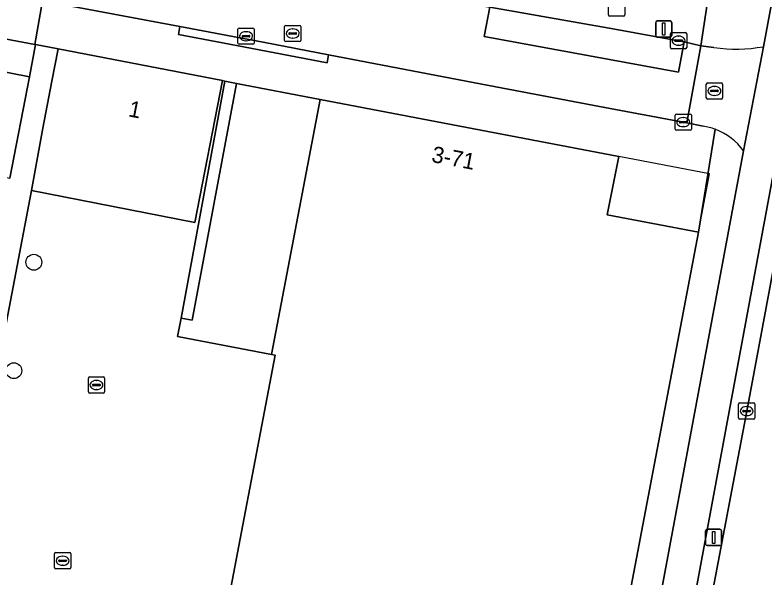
# Model space of a CAD drawing. Extents: x 161402 to 161933, y 381647 to 382315.
# Drawn here: x 161841.65 to 161887.93, y 381908.84 to 381943.55 of the extents above; entities that cross this region are included whole.
import ezdxf

# ---------------------------------------------------------------- set-up
doc = ezdxf.new("R2010")
doc.units = 0
for name, color, linetype in [('IMGEO_Boom', 7, 'Continuous'), ('IMGEO_Brandkraan', 7, 'Continuous'), ('IMGEO_Erf', 7, 'Continuous'), ('IMGEO_Fietspad_gesloten', 7, 'Continuous'), ('IMGEO_Kolk', 7, 'Continuous'), ('IMGEO_Lichtmast', 7, 'Continuous'), ('IMGEO_Pand', 7, 'Continuous'), ('IMGEO_Pand_nummerreeks', 7, 'Continuous'), ('IMGEO_Pand_overbouw', 7, 'Continuous'), ('IMGEO_Parkeervlak_open', 7, 'Continuous'), ('IMGEO_Rijbaan_lokaal_gesloten', 7, 'Continuous'), ('IMGEO_Rijbaan_lokaal_open', 7, 'Continuous'), ('IMGEO_Rioolput', 7, 'Continuous'), ('IMGEO_Verkeerseiland_open', 7, 'Continuous'), ('IMGEO_Voetpad_open', 7, 'Continuous')]:
    doc.layers.add(name, color=color, linetype=linetype)

msp = doc.modelspace()

# ---------------------------------------------------------------- linework, layer by layer
at = {"layer": 'IMGEO_Boom'}
for centre in [(161842.814, 381928.279), (161841.582, 381921.58)]:
    msp.add_circle(centre, 0.489, dxfattribs=at)
at = {"layer": 'IMGEO_Brandkraan'}
for p, q in [((161878.324, 381943.55), (161878.324, 381944.402)), ((161879.325, 381944.402), (161879.325, 381943.55)), ((161879.251, 381943.476), (161878.399, 381943.476))]:
    msp.add_line(p, q, dxfattribs=at)
for points in [[(161878.324, 381943.55), (161878.324, 381944.402)], [(161879.325, 381944.402), (161879.325, 381943.55)], [(161879.251, 381943.476), (161878.399, 381943.476)]]:
    msp.add_lwpolyline(points, dxfattribs=at)
for centre, start, end in [((161878.401, 381943.552), 181.552, 268.448), ((161878.401, 381943.552), 181.552, 268.448), ((161879.249, 381943.552), 271.552, 358.448), ((161879.249, 381943.552), 271.552, 358.448)]:
    msp.add_arc(centre, 0.0765, start, end, dxfattribs=at)
at = {"layer": 'IMGEO_Erf'}
msp.add_lwpolyline([(161838.964, 381940.425), (161842.548, 381939.733), (161842.921, 381941.724), (161842.874, 381941.733), (161832.159, 381943.741)], dxfattribs=at)
at = {"layer": 'IMGEO_Fietspad_gesloten'}
for points in [[(161910.061, 382061.001), (161905.702, 382037.375), (161898.752, 382000), (161887.89, 381941.593), (161886.669, 381935.154), (161880.56, 381902.497), (161879.486, 381896.758), (161857.65, 381780.798), (161851.928, 381750), (161842.232, 381697.819)], [(161881.54, 381896.271), (161882.623, 381902.093), (161888.398, 381933.147), (161890.059, 381942.083), (161900.83, 382000), (161908.061, 382038.88), (161912.039, 382060.567)]]:
    msp.add_lwpolyline(points, dxfattribs=at)
at = {"layer": 'IMGEO_Kolk'}
for p, q in [((161855.426, 381941.812), (161855.426, 381942.664)), ((161855.501, 381942.738), (161856.353, 381942.738)), ((161855.914, 381942.518), (161855.939, 381942.518)), ((161856.427, 381942.664), (161856.427, 381941.812)), ((161882.224, 381942.463), (161883.076, 381942.463)), ((161855.685, 381942.232), (161855.685, 381942.244)), ((161856.123, 381942.195), (161855.725, 381942.195)), ((161855.728, 381942.281), (161856.126, 381942.281)), ((161855.937, 381941.958), (161855.912, 381941.958)), ((161856.169, 381942.244), (161856.169, 381942.232)), ((161882.149, 381941.537), (161882.149, 381942.389)), ((161882.408, 381941.957), (161882.408, 381941.969)), ((161882.451, 381942.006), (161882.849, 381942.006)), ((161882.637, 381942.243), (161882.662, 381942.243)), ((161882.892, 381941.969), (161882.892, 381941.957)), ((161883.15, 381942.389), (161883.15, 381941.537)), ((161856.353, 381941.738), (161855.501, 381941.738)), ((161882.846, 381941.92), (161882.448, 381941.92)), ((161882.66, 381941.683), (161882.635, 381941.683)), ((161883.076, 381941.463), (161882.224, 381941.463)), ((161882.439, 381936.507), (161882.439, 381937.359)), ((161882.514, 381937.433), (161883.366, 381937.433)), ((161883.44, 381937.359), (161883.44, 381936.507)), ((161882.698, 381936.927), (161882.698, 381936.939)), ((161883.136, 381936.89), (161882.738, 381936.89)), ((161882.741, 381936.976), (161883.139, 381936.976)), ((161882.927, 381937.213), (161882.952, 381937.213)), ((161883.182, 381936.939), (161883.182, 381936.927)), ((161883.366, 381936.433), (161882.514, 381936.433)), ((161882.95, 381936.653), (161882.925, 381936.653)), ((161846.259, 381921.198), (161847.111, 381921.198)), ((161846.184, 381920.272), (161846.184, 381921.124)), ((161846.443, 381920.692), (161846.443, 381920.704)), ((161846.486, 381920.741), (161846.884, 381920.741)), ((161846.672, 381920.978), (161846.697, 381920.978)), ((161846.927, 381920.704), (161846.927, 381920.692)), ((161847.185, 381921.124), (161847.185, 381920.272)), ((161846.881, 381920.655), (161846.483, 381920.655)), ((161846.695, 381920.418), (161846.67, 381920.418)), ((161847.111, 381920.198), (161846.259, 381920.198)), ((161886.355, 381918.662), (161886.355, 381919.514)), ((161886.43, 381919.588), (161887.282, 381919.588)), ((161886.843, 381919.368), (161886.868, 381919.368)), ((161887.356, 381919.514), (161887.356, 381918.662)), ((161886.614, 381919.082), (161886.614, 381919.094)), ((161887.052, 381919.045), (161886.654, 381919.045)), ((161886.657, 381919.131), (161887.055, 381919.131)), ((161887.098, 381919.094), (161887.098, 381919.082)), ((161887.282, 381918.588), (161886.43, 381918.588)), ((161886.866, 381918.808), (161886.841, 381918.808)), ((161844.094, 381909.419), (161844.094, 381910.271)), ((161844.169, 381910.345), (161845.021, 381910.345)), ((161844.582, 381910.125), (161844.607, 381910.125)), ((161845.095, 381910.271), (161845.095, 381909.419)), ((161844.353, 381909.839), (161844.353, 381909.851)), ((161844.791, 381909.802), (161844.393, 381909.802)), ((161844.396, 381909.888), (161844.794, 381909.888)), ((161844.605, 381909.565), (161844.58, 381909.565)), ((161844.837, 381909.851), (161844.837, 381909.839)), ((161845.021, 381909.345), (161844.169, 381909.345))]:
    msp.add_line(p, q, dxfattribs=at)
for points in [[(161855.426, 381941.812), (161855.426, 381942.664)], [(161855.501, 381942.738), (161856.353, 381942.738)], [(161856.427, 381942.664), (161856.427, 381941.812)], [(161882.224, 381942.463), (161883.076, 381942.463)], [(161882.149, 381941.537), (161882.149, 381942.389)], [(161883.15, 381942.389), (161883.15, 381941.537)], [(161856.353, 381941.738), (161855.501, 381941.738)], [(161883.076, 381941.463), (161882.224, 381941.463)], [(161882.439, 381936.507), (161882.439, 381937.359)], [(161882.514, 381937.433), (161883.366, 381937.433)], [(161883.44, 381937.359), (161883.44, 381936.507)], [(161883.366, 381936.433), (161882.514, 381936.433)], [(161846.259, 381921.198), (161847.111, 381921.198)], [(161846.184, 381920.272), (161846.184, 381921.124)], [(161847.185, 381921.124), (161847.185, 381920.272)], [(161847.111, 381920.198), (161846.259, 381920.198)], [(161886.355, 381918.662), (161886.355, 381919.514)], [(161886.43, 381919.588), (161887.282, 381919.588)], [(161887.356, 381919.514), (161887.356, 381918.662)], [(161887.282, 381918.588), (161886.43, 381918.588)], [(161844.094, 381909.419), (161844.094, 381910.271)], [(161844.169, 381910.345), (161845.021, 381910.345)], [(161845.095, 381910.271), (161845.095, 381909.419)], [(161845.021, 381909.345), (161844.169, 381909.345)]]:
    msp.add_lwpolyline(points, dxfattribs=at)
for centre, radius, start, end in [((161855.503, 381942.662), 0.0765, 91.552, 178.448), ((161855.503, 381942.662), 0.0765, 91.552, 178.448), ((161856.351, 381942.662), 0.0765, 1.552, 88.448), ((161856.351, 381942.662), 0.0765, 1.552, 88.448), ((161882.226, 381942.387), 0.0765, 91.552, 178.448), ((161882.226, 381942.387), 0.0765, 91.552, 178.448), ((161883.074, 381942.387), 0.0765, 1.552, 88.448), ((161883.074, 381942.387), 0.0765, 1.552, 88.448), ((161855.725, 381942.241), 0.0403, 85.8775, 175.7526), ((161855.722, 381942.231), 0.0366, 178.938, 274.7102), ((161856.126, 381942.238), 0.043, 264.8664, 352.4533), ((161856.13, 381942.243), 0.0386, 1.7309, 96.639), ((161882.448, 381941.966), 0.0403, 85.8775, 175.7526), ((161882.445, 381941.956), 0.0366, 178.938, 274.7102), ((161882.849, 381941.963), 0.043, 264.8664, 352.4533), ((161882.853, 381941.968), 0.0386, 1.7309, 96.639), ((161855.503, 381941.814), 0.0765, 181.552, 268.448), ((161855.503, 381941.814), 0.0765, 181.552, 268.448), ((161856.351, 381941.814), 0.0765, 271.552, 358.448), ((161856.351, 381941.814), 0.0765, 271.552, 358.448), ((161882.226, 381941.539), 0.0765, 181.552, 268.448), ((161882.226, 381941.539), 0.0765, 181.552, 268.448), ((161883.074, 381941.539), 0.0765, 271.552, 358.448), ((161883.074, 381941.539), 0.0765, 271.552, 358.448), ((161882.516, 381937.357), 0.0765, 91.552, 178.448), ((161882.516, 381937.357), 0.0765, 91.552, 178.448), ((161883.364, 381937.357), 0.0765, 1.552, 88.448), ((161883.364, 381937.357), 0.0765, 1.552, 88.448), ((161882.738, 381936.936), 0.0403, 85.8775, 175.7526), ((161882.735, 381936.926), 0.0366, 178.938, 274.7102), ((161883.139, 381936.933), 0.043, 264.8664, 352.4533), ((161883.143, 381936.938), 0.0386, 1.7309, 96.639), ((161882.516, 381936.509), 0.0765, 181.552, 268.448), ((161882.516, 381936.509), 0.0765, 181.552, 268.448), ((161883.364, 381936.509), 0.0765, 271.552, 358.448), ((161883.364, 381936.509), 0.0765, 271.552, 358.448), ((161846.261, 381921.122), 0.0765, 91.552, 178.448), ((161846.261, 381921.122), 0.0765, 91.552, 178.448), ((161847.109, 381921.122), 0.0765, 1.552, 88.448), ((161847.109, 381921.122), 0.0765, 1.552, 88.448), ((161846.483, 381920.701), 0.0403, 85.8775, 175.7526), ((161846.48, 381920.691), 0.0366, 178.938, 274.7102), ((161846.884, 381920.698), 0.043, 264.8664, 352.4533), ((161846.888, 381920.703), 0.0386, 1.7309, 96.639), ((161846.261, 381920.274), 0.0765, 181.552, 268.448), ((161846.261, 381920.274), 0.0765, 181.552, 268.448), ((161847.109, 381920.274), 0.0765, 271.552, 358.448), ((161847.109, 381920.274), 0.0765, 271.552, 358.448), ((161886.432, 381919.512), 0.0765, 91.552, 178.448), ((161886.432, 381919.512), 0.0765, 91.552, 178.448), ((161887.28, 381919.512), 0.0765, 1.552, 88.448), ((161887.28, 381919.512), 0.0765, 1.552, 88.448), ((161886.654, 381919.091), 0.0403, 85.8775, 175.7526), ((161886.651, 381919.081), 0.0366, 178.938, 274.7102), ((161887.055, 381919.088), 0.043, 264.8664, 352.4533), ((161887.059, 381919.093), 0.0386, 1.7309, 96.639), ((161886.432, 381918.664), 0.0765, 181.552, 268.448), ((161886.432, 381918.664), 0.0765, 181.552, 268.448), ((161887.28, 381918.664), 0.0765, 271.552, 358.448), ((161887.28, 381918.664), 0.0765, 271.552, 358.448), ((161844.171, 381910.269), 0.0765, 91.552, 178.448), ((161844.171, 381910.269), 0.0765, 91.552, 178.448), ((161845.019, 381910.269), 0.0765, 1.552, 88.448), ((161845.019, 381910.269), 0.0765, 1.552, 88.448), ((161844.393, 381909.848), 0.0403, 85.8775, 175.7526), ((161844.39, 381909.838), 0.0366, 178.938, 274.7102), ((161844.794, 381909.845), 0.043, 264.8664, 352.4533), ((161844.798, 381909.85), 0.0386, 1.7309, 96.639), ((161844.171, 381909.421), 0.0765, 181.552, 268.448), ((161844.171, 381909.421), 0.0765, 181.552, 268.448), ((161845.019, 381909.421), 0.0765, 271.552, 358.448), ((161845.019, 381909.421), 0.0765, 271.552, 358.448)]:
    msp.add_arc(centre, radius, start, end, dxfattribs=at)
for centre, major_axis, ratio, start_param, end_param in [((161855.913, 381942.238), (-0.387, 0.002), 0.722429, 4.712389, 7.853982), ((161855.938, 381942.238), (-0.39, 0.002), 0.717154, 1.570796, 4.712389), ((161882.636, 381941.963), (-0.387, 0.002), 0.722429, 4.712389, 7.853982), ((161882.661, 381941.963), (-0.39, 0.002), 0.717154, 1.570796, 4.712389), ((161882.926, 381936.933), (-0.387, 0.002), 0.722429, 4.712389, 7.853982), ((161882.951, 381936.933), (-0.39, 0.002), 0.717154, 1.570796, 4.712389), ((161846.671, 381920.698), (-0.387, 0.002), 0.722429, 4.712389, 7.853982), ((161846.696, 381920.698), (-0.39, 0.002), 0.717154, 1.570796, 4.712389), ((161886.842, 381919.088), (-0.387, 0.002), 0.722429, 4.712389, 7.853982), ((161886.867, 381919.088), (-0.39, 0.002), 0.717154, 1.570796, 4.712389), ((161844.581, 381909.845), (-0.387, 0.002), 0.722429, 4.712389, 7.853982), ((161844.606, 381909.845), (-0.39, 0.002), 0.717154, 1.570796, 4.712389)]:
    msp.add_ellipse(centre, major_axis=major_axis, ratio=ratio, start_param=start_param, end_param=end_param, dxfattribs=at)
at = {"layer": 'IMGEO_Lichtmast'}
for p, q in [((161881.235, 381942.286), (161881.235, 381943.086)), ((161881.235, 381943.086), (161881.235, 381942.286)), ((161881.335, 381943.186), (161882.125, 381943.186)), ((161882.125, 381943.186), (161881.335, 381943.186)), ((161882.225, 381943.086), (161882.225, 381942.286)), ((161882.225, 381942.286), (161882.225, 381943.086)), ((161882.125, 381942.186), (161881.335, 381942.186)), ((161881.335, 381942.186), (161882.125, 381942.186)), ((161884.316, 381910.885), (161884.316, 381911.685)), ((161884.316, 381911.685), (161884.316, 381910.885)), ((161884.416, 381911.785), (161885.206, 381911.785)), ((161885.206, 381911.785), (161884.416, 381911.785)), ((161885.306, 381911.685), (161885.306, 381910.885)), ((161885.306, 381910.885), (161885.306, 381911.685)), ((161885.206, 381910.785), (161884.416, 381910.785)), ((161884.416, 381910.785), (161885.206, 381910.785))]:
    msp.add_line(p, q, dxfattribs=at)
for points in [[(161881.655, 381943.061), (161881.805, 381943.061), (161881.805, 381942.311), (161881.655, 381942.311), (161881.655, 381943.061)], [(161884.736, 381911.66), (161884.886, 381911.66), (161884.886, 381910.91), (161884.736, 381910.91), (161884.736, 381911.66)]]:
    msp.add_lwpolyline(points, dxfattribs=at)
for centre, start, end in [((161881.335, 381943.086), 90, 180), ((161881.335, 381943.086), 90, 180), ((161882.125, 381943.086), 0, 90), ((161882.125, 381943.086), 360, 90), ((161881.335, 381942.286), 180, 270), ((161881.335, 381942.286), 180, 270), ((161882.125, 381942.286), 270, 0), ((161882.125, 381942.286), 270, 0), ((161884.416, 381911.685), 90, 180), ((161884.416, 381911.685), 90, 180), ((161885.206, 381911.685), 0, 90), ((161885.206, 381911.685), 360, 90), ((161884.416, 381910.885), 180, 270), ((161884.416, 381910.885), 180, 270), ((161885.206, 381910.885), 270, 0), ((161885.206, 381910.885), 270, 0)]:
    msp.add_arc(centre, 0.1, start, end, dxfattribs=at)
at = {"layer": 'IMGEO_Pand'}
for points in [[(161843.932, 381939.466), (161843.371, 381936.554), (161842.669, 381932.702), (161852.77, 381930.725), (161854.463, 381939.508), (161844.317, 381941.463)], [(161838.964, 381940.425), (161837.754, 381934.157), (161841.338, 381933.465), (161842.548, 381939.733)], [(161854.619, 381939.456), (161851.911, 381924.831), (161852.608, 381924.706), (161855.327, 381939.321)], [(161853.582, 381886.372), (161856.391, 381885.835), (161874.777, 381882.317), (161878.687, 381902.863), (161883.878, 381930.136), (161878.246, 381931.217), (161878.948, 381934.818), (161860.503, 381938.326), (161857.498, 381922.591), (161857.717, 381922.54), (161850.925, 381886.881)]]:
    msp.add_lwpolyline(points, close=True, dxfattribs=at)
at = {"layer": 'IMGEO_Pand_overbouw'}
for points in [[(161855.327, 381939.321), (161852.608, 381924.706), (161851.911, 381924.831), (161851.702, 381923.695), (161857.498, 381922.591), (161860.503, 381938.326)], [(161883.878, 381930.136), (161884.567, 381933.742), (161878.948, 381934.818), (161878.246, 381931.217)]]:
    msp.add_lwpolyline(points, close=True, dxfattribs=at)
at = {"layer": 'IMGEO_Parkeervlak_open'}
for points in [[(161878.707, 381942.675), (161870.982, 381944.038), (161870.647, 381942.219), (161882.653, 381940.012), (161882.997, 381941.882), (161882.65, 381941.962)], [(161857.717, 381922.54), (161857.498, 381922.591), (161851.702, 381923.695), (161851.911, 381924.831), (161854.619, 381939.456), (161854.463, 381939.508), (161852.77, 381930.725), (161842.669, 381932.702), (161835.006, 381892.594), (161839.967, 381889.053), (161842.348, 381888.535), (161845.156, 381887.993), (161847.965, 381887.452), (161850.773, 381886.91), (161850.925, 381886.881)]]:
    msp.add_lwpolyline(points, close=True, dxfattribs=at)
at = {"layer": 'IMGEO_Rijbaan_lokaal_gesloten'}
msp.add_lwpolyline([(161891.107, 381941.989), (161889.505, 381933.058), (161889.483, 381932.953), (161889.257, 381931.885), (161886.857, 381919.088), (161884.634, 381907.375), (161884.615, 381907.144)], dxfattribs=at)
at = {"layer": 'IMGEO_Rijbaan_lokaal_open'}
for points in [[(161870.982, 381944.038), (161868.335, 381944.505), (161867.265, 381944.7), (161856.849, 381946.602), (161850.705, 381947.765), (161850.381, 381946.002), (161843.908, 381947.189), (161843.358, 381944.434), (161851.839, 381942.835), (161855.435, 381942.157), (161856.984, 381941.865), (161861.026, 381941.093), (161870.929, 381939.2), (161877.762, 381937.889), (161882.94, 381936.934), (161883.165, 381936.881), (161884.023, 381941.644), (161882.997, 381941.882), (161882.653, 381940.012), (161870.647, 381942.219)], [(161855.327, 381939.321), (161852.608, 381924.706), (161851.911, 381924.831), (161851.702, 381923.695), (161857.498, 381922.591), (161860.503, 381938.326)]]:
    msp.add_lwpolyline(points, close=True, dxfattribs=at)
for points in [[(161884.837, 381941.542), (161884.023, 381941.644), (161883.165, 381936.881), (161884.172, 381936.679)], [(161886.669, 381935.154), (161887.89, 381941.593)]]:
    msp.add_lwpolyline(points, dxfattribs=at)
for centre, radius, start, end in [((161886.211, 381950.714), 9.274, 261.4821, 280.432), ((161883.62, 381932.978), 3.742, 69.7638, 81.5106), ((161883.611, 381932.955), 3.766, 35.7179, 69.7628)]:
    msp.add_arc(centre, radius, start, end, dxfattribs=at)
at = {"layer": 'IMGEO_Rioolput'}
for p, q in [((161858.384, 381942.905), (161859.236, 381942.905)), ((161858.309, 381941.979), (161858.309, 381942.831)), ((161858.611, 381942.448), (161859.009, 381942.448)), ((161858.797, 381942.685), (161858.822, 381942.685)), ((161859.31, 381942.831), (161859.31, 381941.979)), ((161858.568, 381942.399), (161858.568, 381942.411)), ((161859.006, 381942.362), (161858.608, 381942.362)), ((161858.82, 381942.125), (161858.795, 381942.125)), ((161859.052, 381942.411), (161859.052, 381942.399)), ((161859.236, 381941.905), (161858.384, 381941.905)), ((161884.362, 381938.433), (161884.362, 381939.285)), ((161884.437, 381939.359), (161885.289, 381939.359)), ((161885.363, 381939.285), (161885.363, 381938.433)), ((161884.621, 381938.853), (161884.621, 381938.865)), ((161885.059, 381938.816), (161884.661, 381938.816)), ((161884.664, 381938.902), (161885.062, 381938.902)), ((161884.85, 381939.139), (161884.875, 381939.139)), ((161885.105, 381938.865), (161885.105, 381938.853)), ((161885.289, 381938.359), (161884.437, 381938.359)), ((161884.873, 381938.579), (161884.848, 381938.579))]:
    msp.add_line(p, q, dxfattribs=at)
for points in [[(161858.384, 381942.905), (161859.236, 381942.905)], [(161858.309, 381941.979), (161858.309, 381942.831)], [(161859.31, 381942.831), (161859.31, 381941.979)], [(161859.236, 381941.905), (161858.384, 381941.905)], [(161884.362, 381938.433), (161884.362, 381939.285)], [(161884.437, 381939.359), (161885.289, 381939.359)], [(161885.363, 381939.285), (161885.363, 381938.433)], [(161885.289, 381938.359), (161884.437, 381938.359)]]:
    msp.add_lwpolyline(points, dxfattribs=at)
for centre, radius, start, end in [((161858.386, 381942.829), 0.0765, 91.552, 178.448), ((161858.386, 381942.829), 0.0765, 91.552, 178.448), ((161859.234, 381942.829), 0.0765, 1.552, 88.448), ((161859.234, 381942.829), 0.0765, 1.552, 88.448), ((161858.608, 381942.408), 0.0403, 85.8775, 175.7526), ((161859.013, 381942.41), 0.0386, 1.7309, 96.639), ((161858.386, 381941.981), 0.0765, 181.552, 268.448), ((161858.386, 381941.981), 0.0765, 181.552, 268.448), ((161858.605, 381942.398), 0.0366, 178.938, 274.7102), ((161859.009, 381942.405), 0.043, 264.8664, 352.4533), ((161859.234, 381941.981), 0.0765, 271.552, 358.448), ((161859.234, 381941.981), 0.0765, 271.552, 358.448), ((161884.439, 381939.283), 0.0765, 91.552, 178.448), ((161884.439, 381939.283), 0.0765, 91.552, 178.448), ((161885.287, 381939.283), 0.0765, 1.552, 88.448), ((161885.287, 381939.283), 0.0765, 1.552, 88.448), ((161884.661, 381938.862), 0.0403, 85.8775, 175.7526), ((161884.658, 381938.852), 0.0366, 178.938, 274.7102), ((161885.062, 381938.859), 0.043, 264.8664, 352.4533), ((161885.066, 381938.864), 0.0386, 1.7309, 96.639), ((161884.439, 381938.435), 0.0765, 181.552, 268.448), ((161884.439, 381938.435), 0.0765, 181.552, 268.448), ((161885.287, 381938.435), 0.0765, 271.552, 358.448), ((161885.287, 381938.435), 0.0765, 271.552, 358.448)]:
    msp.add_arc(centre, radius, start, end, dxfattribs=at)
for centre, major_axis, ratio, start_param, end_param in [((161858.796, 381942.405), (-0.387, 0.002), 0.722429, 4.712389, 7.853982), ((161858.821, 381942.405), (-0.39, 0.002), 0.717154, 1.570796, 4.712389), ((161884.849, 381938.859), (-0.387, 0.002), 0.722429, 4.712389, 7.853982), ((161884.874, 381938.859), (-0.39, 0.002), 0.717154, 1.570796, 4.712389)]:
    msp.add_ellipse(centre, major_axis=major_axis, ratio=ratio, start_param=start_param, end_param=end_param, dxfattribs=at)
at = {"layer": 'IMGEO_Verkeerseiland_open'}
for points in [[(161912.039, 382060.567), (161908.061, 382038.88), (161900.83, 382000), (161890.059, 381942.083), (161888.398, 381933.147), (161882.623, 381902.093), (161881.54, 381896.271), (161869.899, 381834.602), (161872.587, 381834.08), (161872.769, 381835.211)], [(161884.615, 381907.144), (161884.634, 381907.375), (161886.857, 381919.088), (161889.257, 381931.885), (161889.483, 381932.953), (161889.505, 381933.058), (161891.107, 381941.989)]]:
    msp.add_lwpolyline(points, dxfattribs=at)
at = {"layer": 'IMGEO_Voetpad_open'}
for points in [[(161887.89, 381941.593), (161898.752, 382000), (161905.702, 382037.375), (161910.061, 382061.001)], [(161825.144, 381952.573), (161826.853, 381952.245), (161835.816, 381950.524), (161841.561, 381949.474), (161844.266, 381948.98), (161844.817, 381948.879), (161850.705, 381947.765), (161856.849, 381946.602), (161856.934, 381947.094), (161867.35, 381945.192), (161867.265, 381944.7), (161868.335, 381944.505), (161870.982, 381944.038), (161878.707, 381942.675), (161882.65, 381941.962), (161882.997, 381941.882), (161884.023, 381941.644), (161884.434, 381944.363)], [(161884.172, 381936.679), (161883.165, 381936.881), (161882.94, 381936.934), (161877.762, 381937.889), (161870.929, 381939.2), (161861.026, 381941.093), (161860.933, 381940.603), (161855.342, 381941.66), (161851.746, 381942.34), (161851.839, 381942.835), (161843.358, 381944.434), (161842.874, 381941.733), (161842.921, 381941.724), (161844.317, 381941.463), (161854.463, 381939.508), (161854.619, 381939.456), (161855.327, 381939.321), (161860.503, 381938.326), (161878.948, 381934.818), (161878.246, 381931.217), (161883.878, 381930.136), (161884.914, 381936.489)], [(161884.434, 381944.363), (161884.023, 381941.644), (161884.837, 381941.542)], [(161835.006, 381892.594), (161842.669, 381932.702), (161843.371, 381936.554), (161843.932, 381939.466), (161844.317, 381941.463), (161842.921, 381941.724), (161842.548, 381939.733), (161841.338, 381933.465)], [(161884.914, 381936.489), (161883.878, 381930.136), (161878.687, 381902.863), (161874.777, 381882.317), (161872.114, 381868.466)], [(161879.486, 381896.758), (161880.56, 381902.497), (161886.669, 381935.154)]]:
    msp.add_lwpolyline(points, dxfattribs=at)
for points in [[(161840.719, 381944.921), (161832.624, 381946.415), (161832.192, 381943.9), (161832.159, 381943.741), (161842.874, 381941.733), (161843.358, 381944.434)], [(161855.435, 381942.157), (161851.839, 381942.835), (161851.746, 381942.34), (161855.342, 381941.66), (161860.933, 381940.603), (161861.026, 381941.093), (161856.984, 381941.865)]]:
    msp.add_lwpolyline(points, close=True, dxfattribs=at)
for centre, radius, start, end in [((161886.211, 381950.714), 9.274, 261.4821, 280.432), ((161883.62, 381932.978), 3.742, 69.7638, 81.5106), ((161883.611, 381932.955), 3.766, 35.7179, 69.7628)]:
    msp.add_arc(centre, radius, start, end, dxfattribs=at)

# ---------------------------------------------------------------- texts
at = {"layer": 'IMGEO_Pand_nummerreeks'}
for s, rotation, p in [('1', 349.0935, (161848.611, 381937.296)), ('3-71', 349.2317, (161867.339, 381934.481))]:
    msp.add_text(s, height=1, rotation=rotation, dxfattribs=at).set_placement(p)

doc.saveas('drawing.dxf')
